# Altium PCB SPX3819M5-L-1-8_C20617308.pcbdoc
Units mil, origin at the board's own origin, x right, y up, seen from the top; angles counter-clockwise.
Board outline 648.04 x 617.09 mil, 2 copper layers (Top Layer, Bottom Layer), stack 0 mil thick; 1 components, 0 nets, 5 pads, 0 vias.
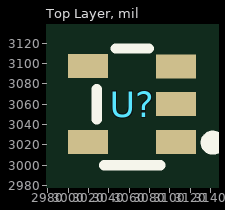
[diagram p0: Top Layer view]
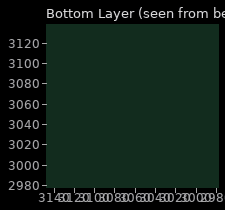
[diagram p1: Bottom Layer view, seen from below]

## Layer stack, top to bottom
Top Layer: signal copper (thickness not stored)
Bottom Layer: signal copper (thickness not stored)

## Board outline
3398.04,2750 2750,2750 2750,3367.09 3398.04,3367.09

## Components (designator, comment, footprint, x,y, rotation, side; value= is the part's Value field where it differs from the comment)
U? "SPX3819M5-L-1-8" SOT-23-5_L2.9-W1.6-P0.95-LS2.8-BR 3063,3060 r0 top

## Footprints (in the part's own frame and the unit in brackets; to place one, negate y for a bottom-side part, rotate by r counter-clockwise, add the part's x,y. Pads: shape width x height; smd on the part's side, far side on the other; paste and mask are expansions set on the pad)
SOT-23-5_L2.9-W1.6-P0.95-LS2.8-BR [mm]
  rect 1x0.6 smd paste+0 mask+0.05: 1(1.1,-0.95) 2(1.1,0) 3(1.1,0.95) 4(-1.1,0.95) 5(-1.1,-0.95)
  silkscreen extent -0.89,-1.52 2.16,1.4

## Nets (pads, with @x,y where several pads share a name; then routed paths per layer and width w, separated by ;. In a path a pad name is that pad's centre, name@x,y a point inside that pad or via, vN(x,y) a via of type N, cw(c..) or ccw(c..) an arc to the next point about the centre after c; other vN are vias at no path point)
pads on no net: U?.1 U?.2 U?.3 U?.4 U?.5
